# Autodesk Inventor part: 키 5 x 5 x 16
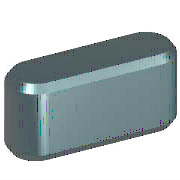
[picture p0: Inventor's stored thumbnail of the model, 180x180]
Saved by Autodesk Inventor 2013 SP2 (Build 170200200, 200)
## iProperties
IsCustomPart: 1
Created: 2012-02
Part Number: 키 5 x 5 x 16
Material: 강철, 연강
Description: 키 및 해당 키홈
Document SubType Name: Modeling
Standard: KS B 1311
Designer: mduedu
Standards Organization: KS
Language: ko-KR
Size Designation: 5 x 5 x 16
Categories: <MemberInstance><Categories><Category DisplayName="샤프트 부품" InternalName="7f7aeb1f-a693-4053-b835-cee3144e0d98" Mnemonic="SHFT"><Category DisplayName="키" Interna
Density: 1 g/cm^3
Author: mduedu
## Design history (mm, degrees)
workplane "Work Plane1"
workplane "Work Plane2"
sketch "스케치1"
  geometry: L1 (2.5, 2.5)-(13.5, 2.5); L2 (13.5, -2.5)-(2.5, -2.5); L3 (0, 9.4)-(0, -7.4) reference; L4 (-5, 0)-(30, 0) reference; L5 (16, 0)-(16, 7); A1 r 2.5 centre (2.5, 0) between (2.5, 2.5) and (2.5, -2.5); A2 r 2.5 centre (13.5, 0) between (13.5, -2.5) and (13.5, 2.5)
  constraints: 6 end point, 5 point on circle, 4 tangent, 3 point on line, 2 centre point, 1 horizontal, 1 parallel, 1 perpendicular
  dimensions: "d0" = 2.5 radius of A1 (= 0.5 x PB); "d13" = 2.5 radius of A2 (= 0.5 x PB); "d14" = 16 distance between parallel lines of L5 L3 (= NLG)
extrude "본체1" new body sketch "스케치1" taper "d3" = 0 deg; stored distance "d4" = 10
workplane "Work Plane3"
body "Solid1"
chamfer "모따기1" distance "d8" = 0.4 (= PHH); stored, may be unused: second distance "d9" = 0.4 (= PHH), angle "d15" = 45 deg
other parameters: "d1" = -3 (= -PNT), "d2" = 2 (= PH - PNT), "NLG" = 16 [user parameter; used in 3 equation terms], "PB" = 5 [user parameter; used in 2 equation terms], "PNT" = 3 [user parameter; used in 2 equation terms], "PH" = 5 [user parameter; used in 1 equation term], "PHH" = 0.4 [user parameter; used in 2 equation terms], "d10" = 0, "d16" = 0, "d17" = 0, "d18" = 0, "WDMIN" = 12 [user parameter], "PLB2" = 16 (= NLG) [user parameter], "WDMAX" = 17 [user parameter], "PLB1" = 16 (= NLG) [user parameter], "RR" = 0.16 [user parameter], "PUEB" = 2.3 [user parameter]
